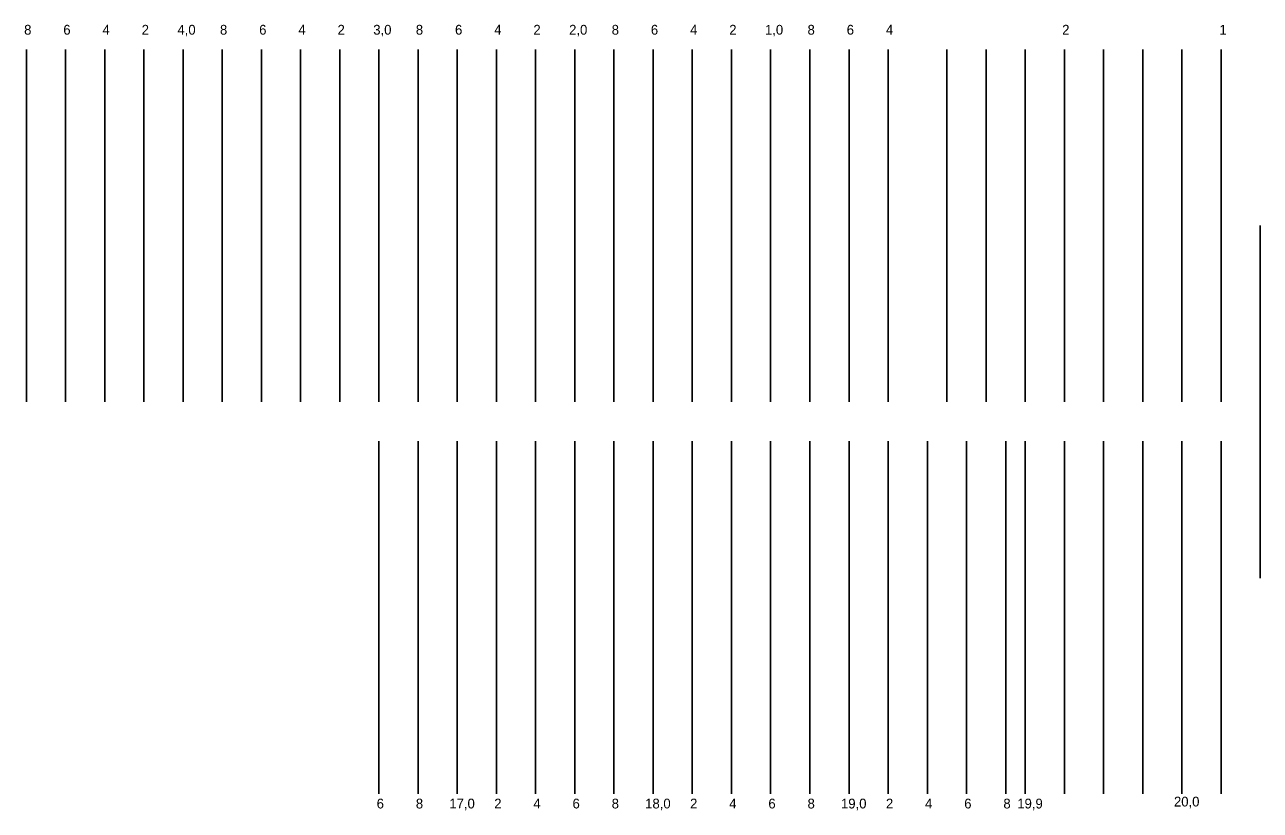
# Model space of a CAD drawing. Extents: x -1424 to 5155, y -2900 to 2050.
# Drawn here: x 1229 to 1860, y -1608 to -1207 of the extents above; entities that cross this region are included whole.
import ezdxf

# ---------------------------------------------------------------- set-up
doc = ezdxf.new("R2010")
doc.units = 0
doc.layers.add('NAVRHOVANÉ', color=7, linetype='Continuous')

msp = doc.modelspace()

# ---------------------------------------------------------------- linework, layer by layer
at = {"layer": 'NAVRHOVANÉ'}
for p, q in [((1230, -1220), (1230, -1400)), ((1250, -1220), (1250, -1400)), ((1270, -1220), (1270, -1400)), ((1290, -1220), (1290, -1400)), ((1310, -1220), (1310, -1400)), ((1330, -1220), (1330, -1400)), ((1350, -1220), (1350, -1400)), ((1370, -1220), (1370, -1400)), ((1390, -1220), (1390, -1400)), ((1410, -1220), (1410, -1400)), ((1430, -1220), (1430, -1400)), ((1450, -1220), (1450, -1400)), ((1470, -1220), (1470, -1400)), ((1490, -1220), (1490, -1400)), ((1510, -1220), (1510, -1400)), ((1530, -1220), (1530, -1400)), ((1550, -1220), (1550, -1400)), ((1570, -1220), (1570, -1400)), ((1590, -1220), (1590, -1400)), ((1610, -1220), (1610, -1400)), ((1630, -1220), (1630, -1400)), ((1650, -1220), (1650, -1400)), ((1670, -1220), (1670, -1400)), ((1700, -1220), (1700, -1400)), ((1720, -1220), (1720, -1400)), ((1740, -1220), (1740, -1400)), ((1760, -1220), (1760, -1400)), ((1780, -1220), (1780, -1400)), ((1800, -1220), (1800, -1400)), ((1820, -1220), (1820, -1400)), ((1840, -1220), (1840, -1400)), ((1860, -1310), (1860, -1490)), ((1410, -1420), (1410, -1600)), ((1430, -1420), (1430, -1600)), ((1450, -1420), (1450, -1600)), ((1470, -1420), (1470, -1600)), ((1490, -1420), (1490, -1600)), ((1510, -1420), (1510, -1600)), ((1530, -1420), (1530, -1600)), ((1550, -1420), (1550, -1600)), ((1570, -1420), (1570, -1600)), ((1590, -1420), (1590, -1600)), ((1610, -1420), (1610, -1600)), ((1630, -1420), (1630, -1600)), ((1650, -1420), (1650, -1600)), ((1670, -1420), (1670, -1600)), ((1690, -1420), (1690, -1600)), ((1710, -1420), (1710, -1600)), ((1730, -1420), (1730, -1600)), ((1740, -1420), (1740, -1600)), ((1760, -1420), (1760, -1600)), ((1780, -1420), (1780, -1600)), ((1800, -1420), (1800, -1600)), ((1820, -1420), (1820, -1600)), ((1840, -1420), (1840, -1600))]:
    msp.add_line(p, q, dxfattribs=at)

# ---------------------------------------------------------------- texts
for s, p in [('8', (1228.83, -1212.5)), ('6', (1248.83, -1212.5)), ('4', (1268.84, -1212.48)), ('2', (1288.85, -1212.5)), ('4,0', (1307.09, -1212.5)), ('8', (1328.83, -1212.5)), ('6', (1348.83, -1212.5)), ('4', (1368.84, -1212.48)), ('2', (1388.85, -1212.5)), ('3,0', (1407.09, -1212.5)), ('8', (1428.83, -1212.5)), ('6', (1448.83, -1212.5)), ('4', (1468.84, -1212.48)), ('2', (1488.85, -1212.5)), ('2,0', (1507.09, -1212.5)), ('8', (1528.83, -1212.5)), ('6', (1548.83, -1212.5)), ('4', (1568.84, -1212.48)), ('2', (1588.85, -1212.5)), ('1,0', (1607.09, -1212.5)), ('8', (1628.83, -1212.5)), ('6', (1648.83, -1212.5)), ('4', (1668.84, -1212.48)), ('2', (1758.85, -1212.5)), ('1', (1839.12, -1212.5)), ('6', (1408.83, -1607.5)), ('8', (1428.83, -1607.5)), ('17,0', (1445.92, -1607.5)), ('2', (1468.85, -1607.5)), ('6', (1508.83, -1607.5)), ('8', (1528.83, -1607.5)), ('18,0', (1545.92, -1607.5)), ('2', (1568.85, -1607.5)), ('6', (1608.83, -1607.5)), ('8', (1628.83, -1607.5)), ('19,0', (1645.92, -1607.5)), ('2', (1668.85, -1607.5)), ('6', (1708.83, -1607.5)), ('8', (1728.83, -1607.5)), ('19,9', (1735.92, -1607.5)), ('20,0', (1815.92, -1606.5)), ('4', (1488.84, -1607.48)), ('4', (1588.84, -1607.48)), ('4', (1688.84, -1607.48))]:
    msp.add_text(s, height=5).set_placement(p)

doc.saveas('drawing.dxf')
